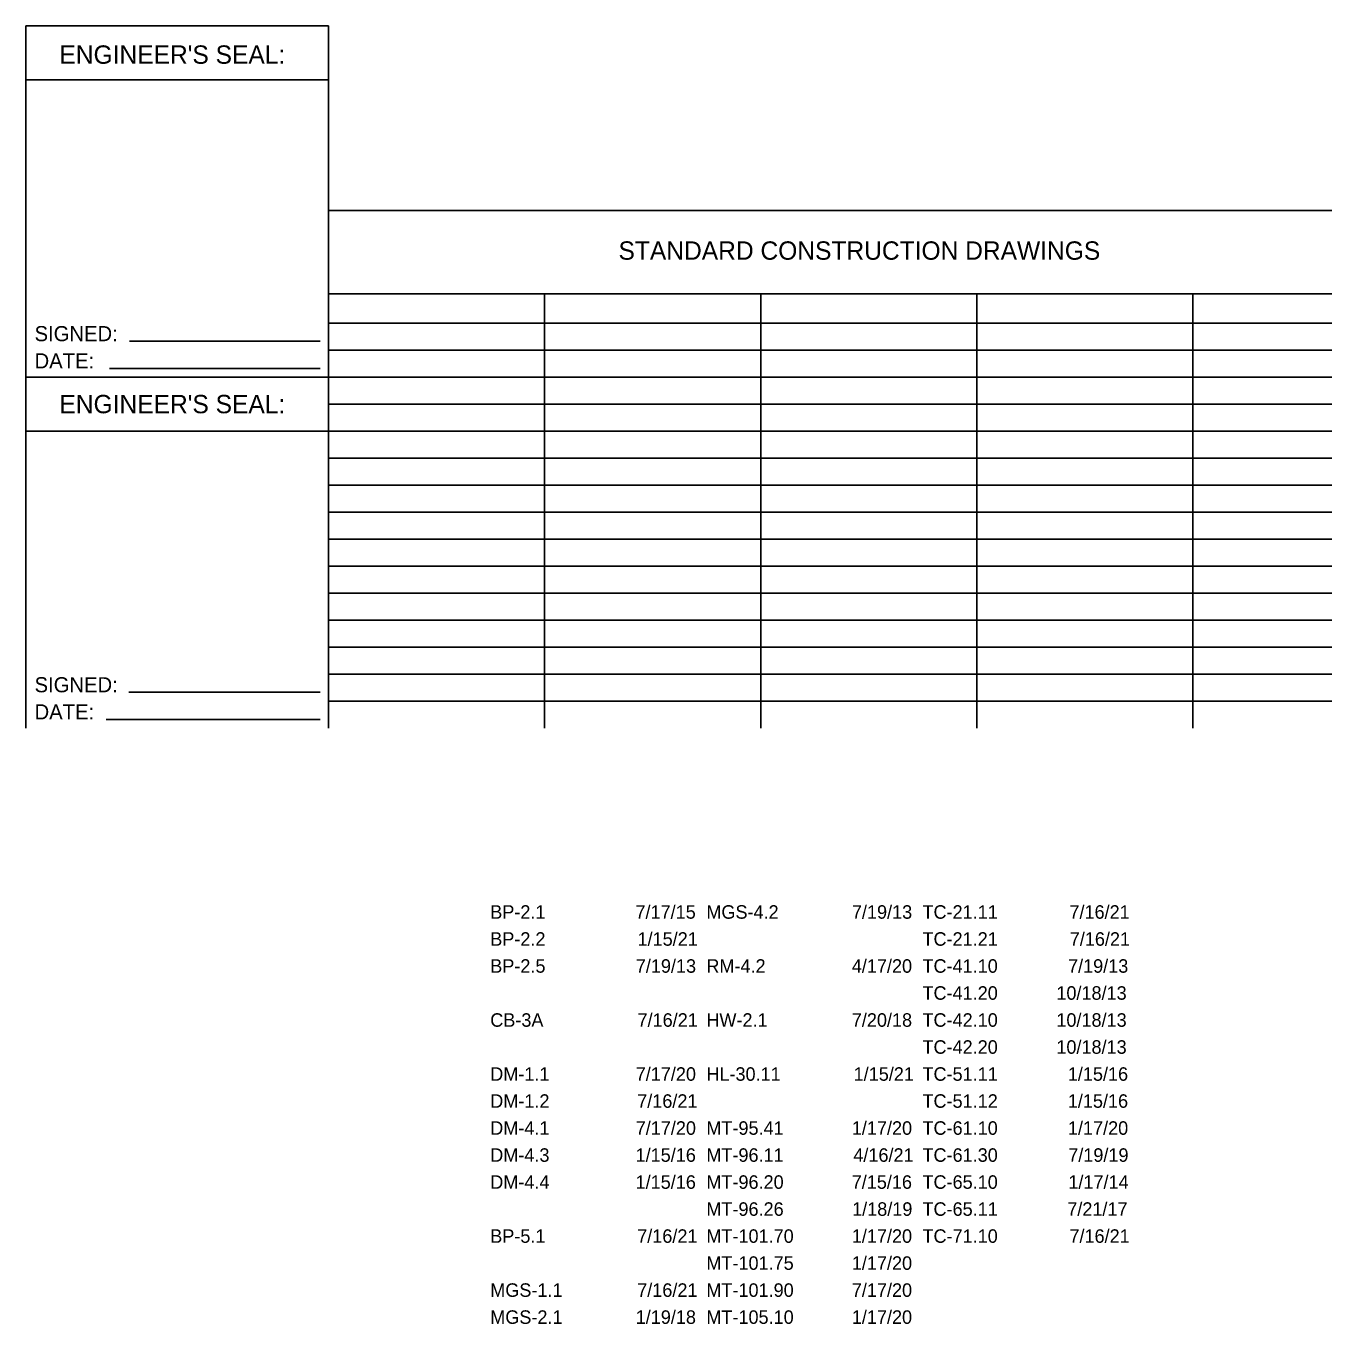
# Model space of a CAD drawing. Extents: x 0 to 64.8, y -5 to 22.
# Drawn here: x 41.44 to 53.44, y -5.02 to 7 of the extents above; entities that cross this region are included whole.
import ezdxf

# ---------------------------------------------------------------- set-up
doc = ezdxf.new("R2010")
doc.units = 0
doc.layers.add('SH_Data', color=7, linetype='Continuous')
doc.layers.add('SH_Text', color=7, linetype='Continuous')

msp = doc.modelspace()

# ---------------------------------------------------------------- linework, layer by layer
at = {"layer": 'SH_Data'}
for p, q in [((41.439, 3.75), (41.439, 7)), ((41.439, 7), (44.239, 7)), ((44.239, 0.5), (44.239, 7)), ((41.439, 6.5), (44.239, 6.5)), ((44.239, 5.292), (57.689, 5.292)), ((44.239, 4.521), (57.689, 4.521)), ((46.239, 0.5), (46.239, 4.521)), ((48.239, 0.5), (48.239, 4.521)), ((50.239, 0.5), (50.239, 4.521)), ((52.239, 0.5), (52.239, 4.521)), ((44.239, 4.25), (57.689, 4.25)), ((44.239, 4), (57.689, 4)), ((41.439, 0.5), (41.439, 3.75)), ((41.439, 3.75), (44.239, 3.75)), ((44.239, 3.75), (57.689, 3.75)), ((44.239, 3.5), (57.689, 3.5)), ((41.439, 3.25), (44.239, 3.25)), ((44.239, 3.25), (57.689, 3.25)), ((44.239, 3), (57.689, 3)), ((44.239, 2.75), (57.689, 2.75)), ((44.239, 2.5), (57.689, 2.5)), ((44.239, 2.25), (57.689, 2.25)), ((44.239, 2), (57.689, 2)), ((44.239, 1.75), (57.689, 1.75)), ((44.239, 1.5), (57.689, 1.5)), ((44.239, 1.25), (57.689, 1.25)), ((44.239, 1), (57.689, 1)), ((44.239, 0.75), (57.689, 0.75))]:
    msp.add_line(p, q, dxfattribs=at)
at = {"layer": 'SH_Text'}
for p, q in [((42.398, 4.082), (44.161, 4.082)), ((42.211, 3.83), (44.161, 3.83)), ((42.39, 0.832), (44.161, 0.832)), ((42.183, 0.581), (44.161, 0.581))]:
    msp.add_line(p, q, dxfattribs=at)

# ---------------------------------------------------------------- texts
for s, height, p in [("ENGINEER'S SEAL:", 0.17, (41.749, 6.65)), ('STANDARD CONSTRUCTION DRAWINGS', 0.17, (46.923, 4.836)), ('SIGNED:', 0.14, (41.519, 4.082)), ('DATE:', 0.14, (41.519, 3.83)), ("ENGINEER'S SEAL:", 0.17, (41.749, 3.415)), ('SIGNED:', 0.14, (41.519, 0.832)), ('DATE:', 0.14, (41.519, 0.581)), ('BP-2.1', 0.125, (45.736, -1.264)), ('7/17/15', 0.125, (47.08, -1.264)), ('MGS-4.2', 0.125, (47.736, -1.264)), ('7/19/13', 0.125, (49.083, -1.264)), ('TC-21.11', 0.125, (49.736, -1.264)), ('7/16/21', 0.125, (51.096, -1.264)), ('BP-2.2', 0.125, (45.736, -1.514)), ('1/15/21', 0.125, (47.099, -1.514)), ('TC-21.21', 0.125, (49.736, -1.514)), ('7/16/21', 0.125, (51.099, -1.514)), ('BP-2.5', 0.125, (45.736, -1.764)), ('7/19/13', 0.125, (47.083, -1.764)), ('RM-4.2', 0.125, (47.736, -1.764)), ('4/17/20', 0.125, (49.082, -1.764)), ('TC-41.10', 0.125, (49.736, -1.764)), ('7/19/13', 0.125, (51.083, -1.764)), ('TC-41.20', 0.125, (49.736, -2.014)), ('10/18/13', 0.125, (50.975, -2.014)), ('CB-3A', 0.125, (45.736, -2.264)), ('7/16/21', 0.125, (47.099, -2.264)), ('HW-2.1', 0.125, (47.736, -2.264)), ('7/20/18', 0.125, (49.082, -2.264)), ('TC-42.10', 0.125, (49.736, -2.264)), ('10/18/13', 0.125, (50.975, -2.264)), ('TC-42.20', 0.125, (49.736, -2.514)), ('10/18/13', 0.125, (50.975, -2.514)), ('DM-1.1', 0.125, (45.736, -2.764)), ('7/17/20', 0.125, (47.082, -2.764)), ('HL-30.11', 0.125, (47.736, -2.764)), ('1/15/21', 0.125, (49.099, -2.764)), ('TC-51.11', 0.125, (49.736, -2.764)), ('1/15/16', 0.125, (51.081, -2.764)), ('7/16/21', 0.125, (47.096, -3.014)), ('1/15/16', 0.125, (51.081, -3.014)), ('DM-1.2', 0.125, (45.736, -3.014)), ('TC-51.12', 0.125, (49.736, -3.014)), ('DM-4.1', 0.125, (45.736, -3.264)), ('7/17/20', 0.125, (47.082, -3.264)), ('MT-95.41', 0.125, (47.736, -3.264)), ('1/17/20', 0.125, (49.082, -3.264)), ('TC-61.10', 0.125, (49.736, -3.264)), ('1/17/20', 0.125, (51.082, -3.264)), ('DM-4.3', 0.125, (45.736, -3.514)), ('1/15/16', 0.125, (47.081, -3.514)), ('MT-96.11', 0.125, (47.736, -3.514)), ('4/16/21', 0.125, (49.096, -3.514)), ('TC-61.30', 0.125, (49.736, -3.514)), ('7/19/19', 0.125, (51.085, -3.514)), ('DM-4.4', 0.125, (45.736, -3.764)), ('1/15/16', 0.125, (47.081, -3.764)), ('MT-96.20', 0.125, (47.736, -3.764)), ('7/15/16', 0.125, (49.081, -3.764)), ('TC-65.10', 0.125, (49.736, -3.764)), ('1/17/14', 0.125, (51.086, -3.764)), ('MT-96.26', 0.125, (47.736, -4.014)), ('1/18/19', 0.125, (49.085, -4.014)), ('TC-65.11', 0.125, (49.736, -4.014)), ('7/21/17', 0.125, (51.076, -4.014)), ('BP-5.1', 0.125, (45.736, -4.264)), ('7/16/21', 0.125, (47.096, -4.264)), ('MT-101.70', 0.125, (47.736, -4.264)), ('1/17/20', 0.125, (49.082, -4.264)), ('TC-71.10', 0.125, (49.736, -4.264)), ('7/16/21', 0.125, (51.096, -4.264)), ('MT-101.75', 0.125, (47.736, -4.514)), ('1/17/20', 0.125, (49.082, -4.514)), ('MGS-1.1', 0.125, (45.736, -4.764)), ('7/16/21', 0.125, (47.096, -4.764)), ('MT-101.90', 0.125, (47.736, -4.764)), ('7/17/20', 0.125, (49.082, -4.764)), ('MGS-2.1', 0.125, (45.736, -5.014)), ('1/19/18', 0.125, (47.082, -5.014)), ('MT-105.10', 0.125, (47.736, -5.014)), ('1/17/20', 0.125, (49.082, -5.014))]:
    msp.add_text(s, height=height, dxfattribs=at).set_placement(p)

doc.saveas('drawing.dxf')
